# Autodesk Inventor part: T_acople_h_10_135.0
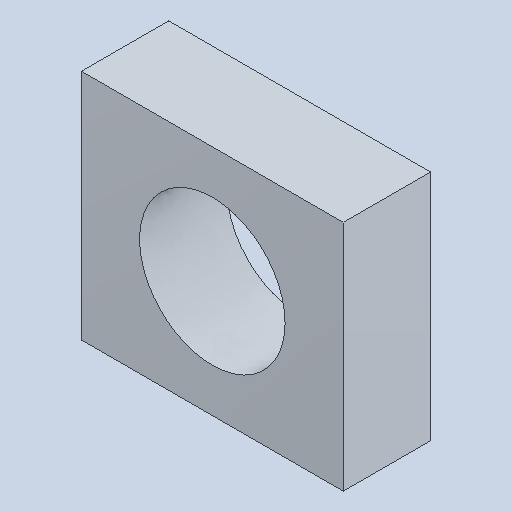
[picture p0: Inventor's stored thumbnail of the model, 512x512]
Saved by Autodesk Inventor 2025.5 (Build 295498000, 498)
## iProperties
Created: 2026-10
Part Number: T_acople_h_10_135.0
Material: Genérico
Document SubType Name: Modeling
Designer: Luis M
Density: 1 g/cm^3
Appearance: Valor por defecto
Author: Luis M
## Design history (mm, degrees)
feature "Base1"
node "Sólido1"
